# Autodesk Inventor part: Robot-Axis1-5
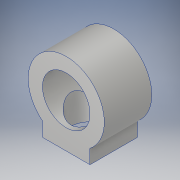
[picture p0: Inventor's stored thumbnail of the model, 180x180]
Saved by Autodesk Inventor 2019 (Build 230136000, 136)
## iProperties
Created: 2018-07
Part Number: Robot-Axis1-5
Material: Aluminum 6061
Description: 123456
Document SubType Name: Modeling
Designer: Power User
Mass: 394.75 g
Surface Area: 293.447 cm^2
Volume: 146.204 cm^3
Density: 2.7 g/cm^3
Appearance: Aluminum - Flat
Title: GEAR
Author: Power User
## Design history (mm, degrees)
sketch "Sketch6"
  geometry: L1 (-25, 16.58)-(25, 16.58); L2 (25, 16.58)-(25, 0); L3 (25, 0)-(-25, 0); L4 (-25, 0)-(-25, 16.58); C1 r 40 at (0, 46.2); C2 r 25 at (0, 46.2); 2 further points
  constraints: 8 end point, 2 centre point, 2 coincident, 2 parallel, 1 horizontal, 1 midpoint, 1 perpendicular
  dimensions: "d44" = 80 diameter of C1; "d45" = 46.2 distance of point (0, 0) C1.centre; "d46" = 50 distance of L2.end L3.end; "d47" = 50 diameter of C2
extrude "Extrusion5" new body sketch "Sketch6" stored distance "d48" = 50; taper "d49" = 0 deg
sketch "Sketch7"
  geometry: C1 r 20 at (25, -25); 1 further point
  constraints: 1 centre point, 1 coincident
  dimensions: "d50" = 40 diameter of C1
extrude "Extrusion6" cut sketch "Sketch7" stored distance "d51" = 50; taper "d52" = 0 deg
body "Solid2"
